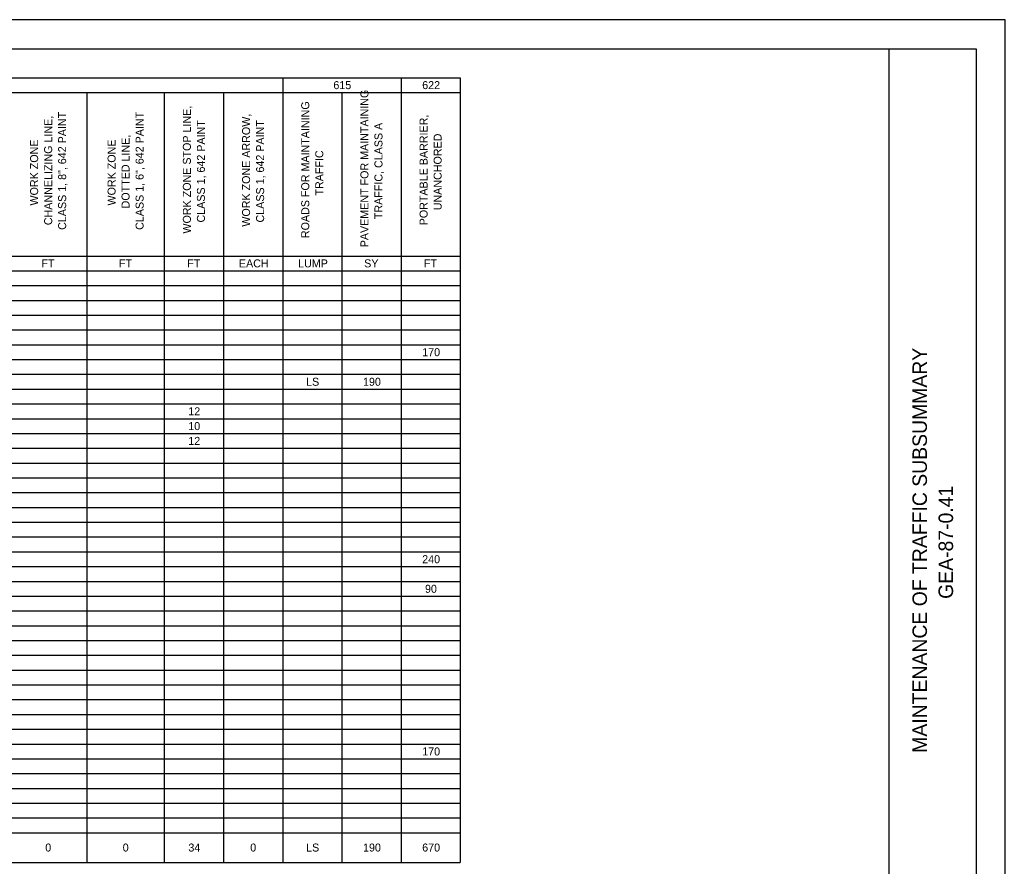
# Model space of a CAD drawing. Extents: x 0 to 34, y 0 to 22.
# Drawn here: x 17.01 to 34, y 7.4 to 22 of the extents above; entities that cross this region are included whole.
import ezdxf

# ---------------------------------------------------------------- set-up
doc = ezdxf.new("R2010")
doc.units = 0
for name, color, linetype in [('SH_Border', 7, 'Continuous'), ('SH_Cut_Line', 7, 'Continuous'), ('SH_Data', 7, 'Continuous'), ('SH_Text', 7, 'Continuous')]:
    doc.layers.add(name, color=color, linetype=linetype)

msp = doc.modelspace()

# ---------------------------------------------------------------- linework, layer by layer
at = {"layer": 'SH_Border'}
msp.add_line((32, 0.5), (32, 21.5), dxfattribs=at)
msp.add_lwpolyline([(1.5, 21.5), (33.5, 21.5), (33.5, 0.5), (1.5, 0.5)], close=True, dxfattribs=at)
at = {"layer": 'SH_Cut_Line'}
msp.add_lwpolyline([(0, 0), (34, 0), (34, 22), (0, 22)], close=True, dxfattribs=at)
at = {"layer": 'SH_Text'}
for p, q in [((2, 21), (24.605, 21)), ((21.545, 21), (21.545, 7.47)), ((23.585, 21), (23.585, 7.47)), ((24.605, 21), (24.605, 7.47)), ((8.045, 20.745), (24.605, 20.745)), ((18.17, 20.745), (18.17, 7.47)), ((19.505, 20.745), (19.505, 7.47)), ((20.525, 20.745), (20.525, 7.47)), ((22.565, 20.745), (22.565, 7.47)), ((8.045, 17.925), (24.605, 17.925)), ((2, 17.67), (24.605, 17.67)), ((2, 17.415), (24.605, 17.415)), ((2, 17.16), (24.605, 17.16)), ((2, 16.905), (24.605, 16.905)), ((2, 16.65), (24.605, 16.65)), ((2, 16.395), (24.605, 16.395)), ((2, 16.14), (24.605, 16.14)), ((2, 15.885), (24.605, 15.885)), ((2, 15.63), (24.605, 15.63)), ((2, 15.375), (24.605, 15.375)), ((2, 15.12), (24.605, 15.12)), ((2, 14.865), (24.605, 14.865)), ((2, 14.61), (24.605, 14.61)), ((2, 14.355), (24.605, 14.355)), ((2, 14.1), (24.605, 14.1)), ((2, 13.845), (24.605, 13.845)), ((2, 13.59), (24.605, 13.59)), ((2, 13.335), (24.605, 13.335)), ((2, 13.08), (24.605, 13.08)), ((2, 12.825), (24.605, 12.825)), ((2, 12.57), (24.605, 12.57)), ((2, 12.315), (24.605, 12.315)), ((2, 12.06), (24.605, 12.06)), ((2, 11.805), (24.605, 11.805)), ((2, 11.55), (24.605, 11.55)), ((2, 11.295), (24.605, 11.295)), ((2, 11.04), (24.605, 11.04)), ((2, 10.785), (24.605, 10.785)), ((2, 10.53), (24.605, 10.53)), ((2, 10.275), (24.605, 10.275)), ((2, 10.02), (24.605, 10.02)), ((2, 9.765), (24.605, 9.765)), ((2, 9.51), (24.605, 9.51)), ((2, 9.255), (24.605, 9.255)), ((2, 9), (24.605, 9)), ((2, 8.745), (24.605, 8.745)), ((2, 8.49), (24.605, 8.49)), ((2, 8.235), (24.605, 8.235)), ((2, 7.98), (24.605, 7.98)), ((2, 7.47), (24.605, 7.47))]:
    msp.add_line(p, q, dxfattribs=at)

# ---------------------------------------------------------------- texts
at = {"layer": 'SH_Data'}
for s, p in [('MAINTENANCE OF TRAFFIC SUBSUMMARY', (32.65, 9.359)), ('GEA-87-0.41', (33.1, 12.013))]:
    msp.add_text(s, height=0.25, rotation=90, dxfattribs=at).set_placement(p)
at = {"layer": 'SH_Text'}
for s, p in [('615', (22.419, 20.803)), ('622', (23.95, 20.803)), ('FT', (17.388, 17.729)), ('FT', (18.723, 17.729)), ('FT', (19.9, 17.729)), ('EACH', (20.791, 17.729)), ('LUMP', (21.811, 17.729)), ('SY', (22.95, 17.729)), ('FT', (23.98, 17.729)), ('170', (23.95, 16.198)), ('LS', (21.949, 15.688)), ('190', (22.93, 15.688)), ('12', (19.918, 15.178)), ('10', (19.918, 14.923)), ('12', (19.918, 14.668)), ('240', (23.95, 12.628)), ('90', (23.998, 12.118)), ('170', (23.95, 9.313)), ('0', (17.453, 7.656)), ('0', (18.788, 7.656)), ('34', (19.92, 7.656)), ('0', (20.986, 7.656)), ('LS', (21.949, 7.656)), ('190', (22.93, 7.656)), ('670', (23.95, 7.656))]:
    msp.add_text(s, height=0.138, dxfattribs=at).set_placement(p)
for s, p in [('PAVEMENT FOR MAINTAINING ', (23.023, 18.076)), ('ROADS FOR MAINTAINING ', (22.003, 18.234)), ('CLASS 1, 8", 642 PAINT', (17.813, 18.376)), ('CLASS 1, 6", 642 PAINT', (19.148, 18.376)), ('WORK ZONE STOP LINE, ', (19.963, 18.312)), ('CHANNELIZING LINE,', (17.572, 18.457)), ('CLASS 1, 642 PAINT', (20.205, 18.503)), ('WORK ZONE ARROW, ', (20.983, 18.431)), ('CLASS 1, 642 PAINT', (21.225, 18.503)), ('TRAFFIC, CLASS A', (23.265, 18.561)), ('PORTABLE BARRIER, ', (24.043, 18.455)), ('WORK ZONE', (17.33, 18.796)), ('WORK ZONE', (18.665, 18.796)), ('DOTTED LINE,', (18.906, 18.746)), ('UNANCHORED', (24.285, 18.714)), ('TRAFFIC', (22.245, 18.968))]:
    msp.add_text(s, height=0.138, rotation=90, dxfattribs=at).set_placement(p)

doc.saveas('drawing.dxf')
